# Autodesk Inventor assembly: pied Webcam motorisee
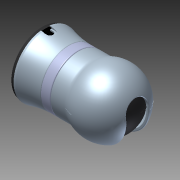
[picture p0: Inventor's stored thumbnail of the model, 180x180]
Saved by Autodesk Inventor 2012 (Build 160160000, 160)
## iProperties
Created: 2013-08
Part Number: pied Webcam motorisee
Document SubType Name: Assembly
Designer: hilarion
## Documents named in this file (6)
- D:\dominique\travail\année 2013-2014\TSTI2D\ITEC\Révision inventor\webcam motorisé\Composants importés\Webcam motorisee\pied Webcam motorisee.iam
- D:\dominique\travail\année 2013-2014\TSTI2D\ITEC\Révision inventor\webcam motorisé\Composants importés\Webcam motorisee\SE-Base.iam
- D:\dominique\travail\année 2013-2014\TSTI2D\ITEC\Révision inventor\webcam motorisé\Composants importés\Webcam motorisee\SE-Camera.iam
- D:\dominique\travail\année 2013-2014\TSTI2D\ITEC\Révision inventor\webcam motorisé\Composants importés\Webcam motorisee\SE-Coques.iam
- D:\dominique\travail\année 2013-2014\TSTI2D\ITEC\Révision inventor\webcam motorisé\Composants importés\Webcam motorisee\sortie_moteur.iam
- D:\dominique\travail\année 2013-2014\TSTI2D\ITEC\Révision inventor\webcam motorisé\Composants importés\Webcam motorisee\Pignon_étagé.iam
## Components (5 placed, 5 different names)
1. SE-Base:1 [sub-assembly]
2. SE-Camera:1 [sub-assembly]
3. SE-Coques:1 [sub-assembly]
4. sortie_moteur:1 [sub-assembly]
5. Pignon_étagé:1 [sub-assembly]
